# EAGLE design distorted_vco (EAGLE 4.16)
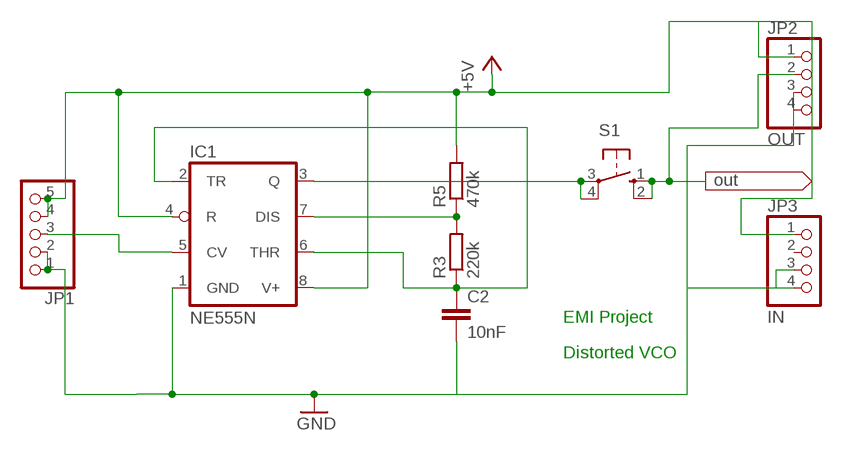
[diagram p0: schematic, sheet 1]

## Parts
C2  10nF  C-EU025-024X044  [C025-024X044]
IC1  NE555N  [DIL08]
JP1  PINHD-1X5  [1X05]
JP2  OUT  PINHD-1X4  [1X04]
JP3  IN  PINHD-1X4  [1X04]
R3  220k  R-EU_0207/7  [0207/7]
R5  470k  R-EU_0207/7  [0207/7]
S1  10-XX  [B3F-10XX]

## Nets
+5V: IC1.4(R) IC1.8(V+) JP1.4 JP1.5 JP2.1 JP3.1 R5.2
GND: C2.2 IC1.1(GND) JP1.1 JP1.2 JP2.3 JP2.4 JP3.3 JP3.4
N$1: IC1.5(CV) JP1.3
N$2: C2.1 IC1.2(TR) IC1.6(THR) R3.1
N$3: JP2.2 S1.1(S) S1.2(S1)
N$4: IC1.3(Q) S1.3(P) S1.4(P1)
N$6: IC1.7(DIS) R3.2 R5.1
Unconnected: JP3.2

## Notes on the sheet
- EMI Project
- Distorted VCO

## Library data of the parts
C2 = rcl:C-EU: CAPACITOR, European symbol
IC1 = linear:*555: TIMER
JP1 = pinhead:PINHD-1X5: PIN HEADER
JP2 JP3 = pinhead:PINHD-1X4: PIN HEADER
R3 R5 = rcl:R-EU_: RESISTOR, European symbol
S1 = switch-omron:10-XX: OMRON SWITCH

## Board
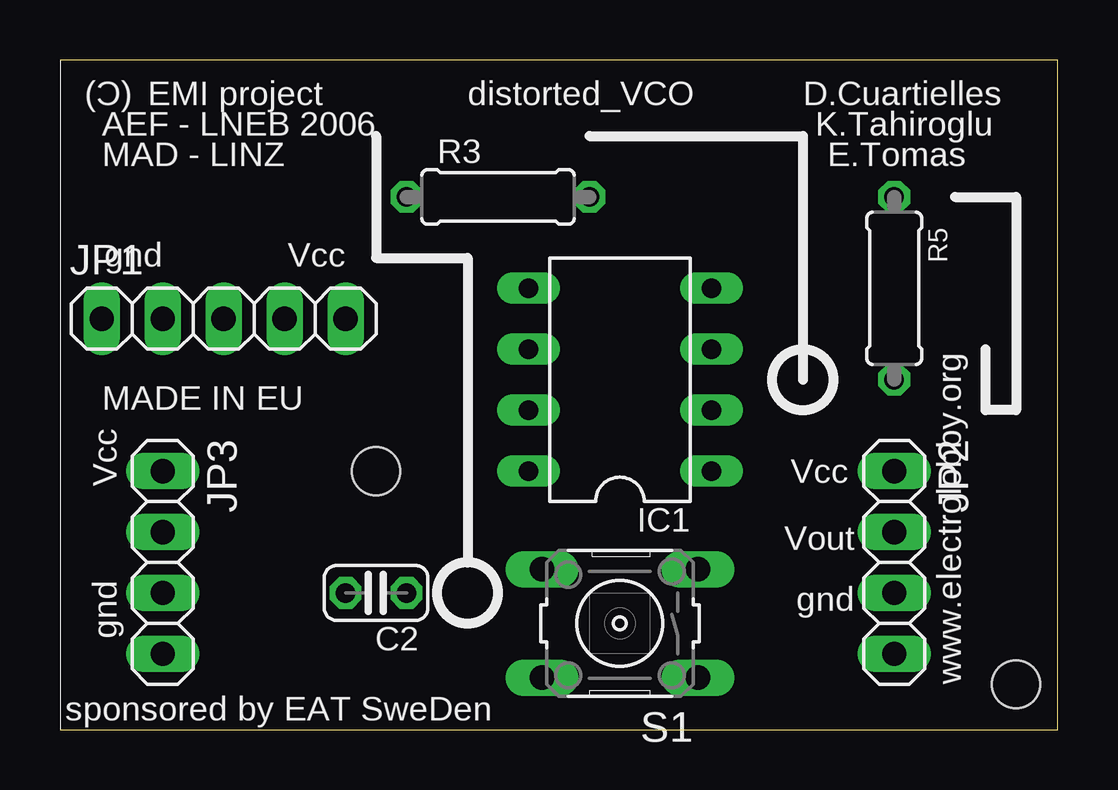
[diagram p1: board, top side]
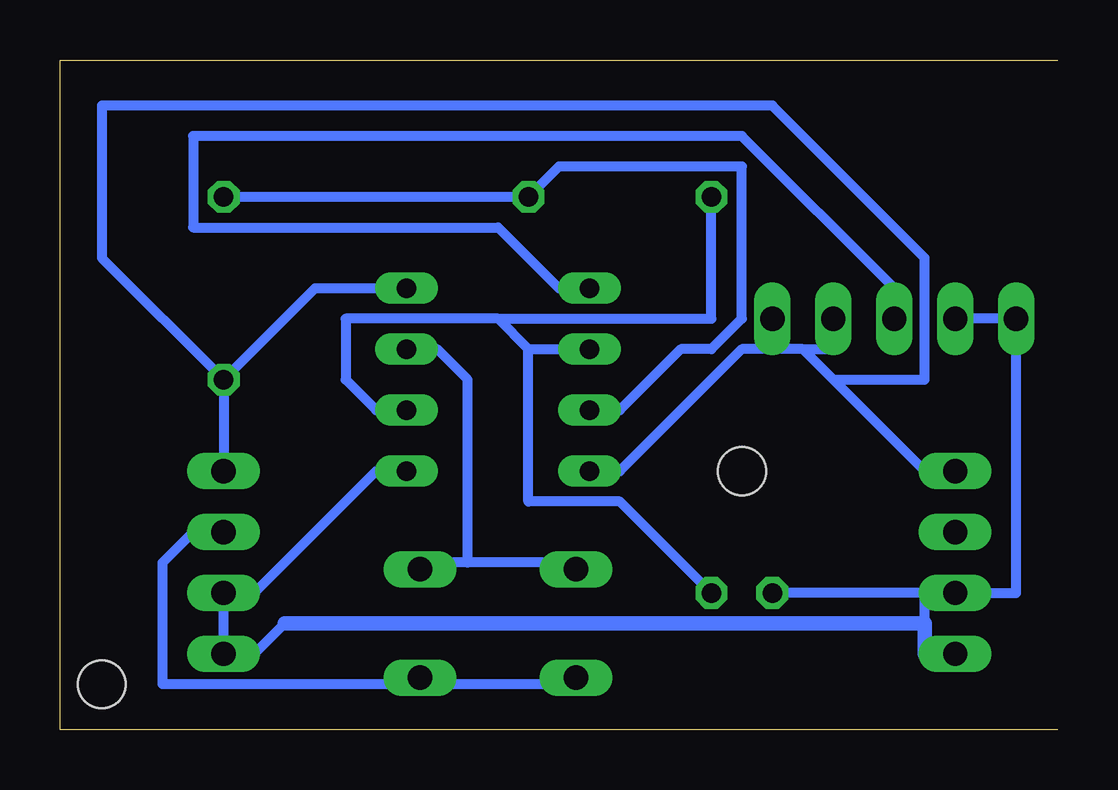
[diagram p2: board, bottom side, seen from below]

Size 41.58 x 27.93 mm. Coordinates in mm from the lower left corner, seen from the top.
Outline: 0,0 41.58,0 41.58,27.93 0,27.93
Copper layers (1*16): Top 0.035mm / dielectric 1.5mm / Bottom 0.035mm
Design rules "default": minimum track width 10mil, minimum drill 24mil, track to track 8mil, track to pad 8mil, pad to pad 8mil, via to via 8mil, smd to smd 8mil, copper to edge 40mil, drill to drill 8mil, minimum pad ring 10mil, minimum via ring 8mil, stop-mask expansion 4mil, vias tented up to drill 0mil, thermal gap 10mil
Holes 2 mm at 39.84,1.9 13.17,10.79

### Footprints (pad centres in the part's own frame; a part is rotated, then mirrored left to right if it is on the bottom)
C025-024X044 = drill 0.813 octagon: 1 -1.27,0; 2 1.27,0
DIL08 = drill 0.813 long: 1 -3.81,-3.81; 2 -1.27,-3.81; 3 1.27,-3.81; 4 3.81,-3.81; 5 3.81,3.81; 6 1.27,3.81; 7 -1.27,3.81; 8 -3.81,3.81
1X05 = drill 1.016 long: 1 -5.08,0; 2 -2.54,0; 3 0,0; 4 2.54,0; 5 5.08,0
1X04 = drill 1.016 long: 1 -3.81,0; 2 -1.27,0; 3 1.27,0; 4 3.81,0
0207/7 = drill 0.813 octagon: 1 -3.81,0; 2 3.81,0
B3F-10XX = drill 1.016 long: 1 -3.251,2.261; 2 3.251,2.261; 3 -3.251,-2.261; 4 3.251,-2.261

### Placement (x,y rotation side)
C2  13.17,5.71 180 top
IC1  23.33,14.6 90 top
JP1  6.82,17.14 0 top
JP2  34.76,6.98 270 top
JP3  4.28,6.98 270 top
R3  18.25,22.22 0 top
R5  34.76,18.41 270 top
S1  23.33,4.44 180 top

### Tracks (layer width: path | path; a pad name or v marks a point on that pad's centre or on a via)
+5V
  Bottom 0.406: R5.2 JP2.1 | R5.2 30.95,18.41 IC1.4 | 11.9,15.87 13.17,15.87 18.25,10.79 IC1.8 | 9.36,14.6 10.63,15.87 | 9.36,14.6 5.55,10.79 JP3.1 | 10.63,15.87 11.9,15.87 | 11.9,15.87 JP1.5 | 10.63,15.87 9.36,15.87 JP1.4 | R5.2 39.84,19.68 39.84,26.03 11.9,26.03 5.55,19.68 5.55,14.6 9.36,14.6
GND
  Bottom 0.406: IC1.1 28.41,10.79 33.49,5.71 JP2.3 JP2.4 33.49,3.17 32.22,4.44 | JP1.2 JP1.1 1.74,5.71 JP3.3 5.55,5.71 | 5.55,5.71 C2.2 | 5.55,4.44 5.55,5.71
  Bottom 0.61: JP3.4 5.55,3.17 5.55,4.44 32.22,4.44
N$1
  Bottom 0.406: IC1.5 20.79,18.41 23.33,20.95 36.03,20.95 36.03,24.76 13.17,24.76 6.82,18.41 JP1.3
N$2
  Bottom 0.406: C2.1 18.25,9.52 22.06,9.52 22.06,15.87 | 22.06,15.87 IC1.6 | 23.33,17.14 29.68,17.14 29.68,14.6 28.41,13.33 IC1.2 | 22.06,15.87 23.33,17.14 | R3.1 14.44,17.14 23.33,17.14
N$3
  Bottom 0.406: S1.2 20.79,1.9 25.87,1.9 S1.1 27.14,1.9 37.3,1.9 37.3,6.98 36.03,8.25 JP2.2
N$4
  Bottom 0.406: 24.6,6.98 24.6,14.6 25.87,15.87 IC1.3 | 24.6,6.98 25.87,6.98 S1.3 | 24.6,6.98 20.79,6.98 S1.4
N$6
  Bottom 0.406: IC1.7 18.25,13.33 15.71,15.87 14.44,15.87 13.17,17.14 13.17,23.49 20.79,23.49 R3.2 R5.1

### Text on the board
tPlace: (C) | EMI project | distorted_VCO | D.Cuartielles | AEF - LNEB 2006 | K.Tahiroglu | MAD - LINZ | E.Tomas | gnd | Vcc | Vcc | Vcc | Vout | gnd | gnd | sponsored by EAT SweDen
tNames: MADE IN EU | www.electrolobby.org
